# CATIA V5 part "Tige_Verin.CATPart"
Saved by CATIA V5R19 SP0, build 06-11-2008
Part number: Verin2
Bounding box of the stored display mesh (mm): x -100 to 105, y -7.954 to 7.954, z -7.954 to 7.954
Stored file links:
  G:\EU_thinkMotion\CFAO_2010\St2M_groupe2\St2M_groupe2\csayed\csayed\csayed\Tige_Verin.CATPart
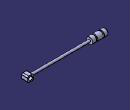
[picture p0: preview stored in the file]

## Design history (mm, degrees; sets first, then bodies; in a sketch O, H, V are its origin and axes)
Body1 (main body)
  Sketch1 on xy-plane, origin (0, 0, 0), H (1, 0, 0), V (0, 1, 0)
    line L1 (-100, 8) -> (-60, 8)
    point P1 (-100, 8)
    point P2 (-60, 8)
    line L2 (-60, 8) -> (-60, 3)
    point P3 (-60, 3)
    line L3 (-60, 3) -> (90, 3)
    line L4 (-100, 8) -> (-100, 0)
    point P5 (-100, 0)
    line L5 (90, 3) -> (90, 0)
    point P6 (90, 0)
    distance P1 H = 8
    distance P1 V = 100
    distance P2 V = 60
    distance P3 H = 3
    length L3 = 150
    horizontal: L1 H, L3 H
    vertical: L2 V, L4 V, L5 V
    coincidence: P5 H, P6 H
  Shaft1: profile Sketch1, axis Sketch1.H, angle 360
  Sketch2 on zx-plane, origin (0, 0, 0), H (-1, 0, 0), V (0, 0, 1)
    line L1 (87, 9) -> (90, 9)
    line L2 (90, 9) -> (90, 5)
    line L3 (90, 5) -> (87, 5)
    line L4 (87, 5) -> (87, 9)
    reference projected line E1 (100, 8) -> (100, -8) from edge [face of Shaft1 from Sketch1.L1 | face of Shaft1 from Sketch1.L4]
    reference projected line E2 through (0, 0) direction (1, 0) from axis of face of Shaft1 from Sketch1.L1
    distance L2 E1 = 10
    distance E2 L3 = 5
    horizontal: L1 H, L3 H
    vertical: L2 V, L4 V
  Groove1: profile Sketch2, axis Sketch2.H, angle 360
  Sketch3 on zx-plane, origin (0, 0, 0), H (-1, 0, 0), V (0, 0, 1)
    line L1 (70, 8.6587) -> (73, 8.6587)
    line L2 (73, 8.6587) -> (73, 4.963)
    line L3 (73, 4.963) -> (70, 4.963)
    line L4 (70, 4.963) -> (70, 8.6587)
    reference projected line E1 (60, 8) -> (60, -8) from edge [face of Shaft1 from Sketch1.L2 | face of Shaft1 from Sketch1.L1]
    reference projected line E2 through (0, 0) direction (1, 0) from axis of face of Shaft1 from Sketch1.L1
    distance E1 L4 = 10
    distance L3 E2 = 4.963
    length L3 = 3
    horizontal: L1 H, L3 H
    vertical: L2 V, L4 V
  Groove2: profile Sketch3, axis Sketch3.H, angle 360
  Fillet1: radius 1, on edge [face of Shaft1 from Sketch1.L1 | face of Shaft1 from Sketch1.L4]
  Sketch4 on face of Shaft1 from Sketch1.L5, origin (90, 0, 0), H (0, 1, 0), V (0, 0, 1)
    line L1 (-7.5, 7) -> (7.5, 7)
    line L2 (7.5, 7) -> (7.5, -7)
    line L3 (7.5, -7) -> (-7.5, -7)
    line L4 (-7.5, -7) -> (-7.5, 7)
    horizontal: L1 H, L3 H
    vertical: L2 V, L4 V
  Pad1: profile Sketch4, direction (1, 0, 0), length 15
  Fillet2: radius 3, on edge [start face of Pad1 | face of Pad1 from Sketch4.L1]; edge [face of Pad1 from Sketch4.L1 | end face of Pad1]; edge [face of Pad1 from Sketch4.L3 | end face of Pad1]; edge [start face of Pad1 | face of Pad1 from Sketch4.L3]
  Sketch5 on face of Pad1 from Sketch4.L4, origin (0, -7.5, 0), H (1, 0, 0), V (0, 0, 1)
    circle A1 centre (97.5, 0) radius 5
    point P1 (97.5, 0)
    reference projected line E1 through (0, 0) direction (-1, 0) from axis of face of Shaft1 from Sketch1.L3
    reference projected line E2 (105, 7) -> (105, -7) from edge [face of Pad1 from Sketch4.L4 | end face of Pad1]
    distance P1 E1 = 0
    distance P1 E2 = 7.5
  Pocket1: profile Sketch5, direction (0, 1, 0), through (limit type 3)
